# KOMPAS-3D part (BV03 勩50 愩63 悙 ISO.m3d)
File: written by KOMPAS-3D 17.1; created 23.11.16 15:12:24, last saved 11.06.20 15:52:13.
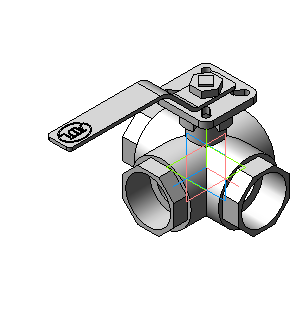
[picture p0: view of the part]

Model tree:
1. Операция без истории:1  (labels: Сталь 20  ГОСТ 1050-88)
